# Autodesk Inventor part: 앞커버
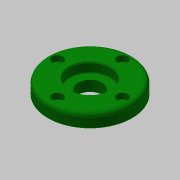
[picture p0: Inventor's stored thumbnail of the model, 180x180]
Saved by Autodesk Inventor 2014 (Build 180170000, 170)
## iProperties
Created: 2015-09
Part Number: 앞커버
Material: 알루미늄 6061
Document SubType Name: Modeling
Designer: mduedu
Density: 1 g/cm^3
Appearance: 진녹색
Author: mduedu
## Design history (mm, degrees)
sketch "스케치1"
  geometry: L1 (0, 7.5)-(0, -7.5); L2 (0, 7.5)-(31, 7.5); L3 (31, 7.5)-(31, -2.5); L4 (31, -2.5)-(17.5, -2.5); L5 (17.5, -2.5)-(17.5, -7.5); L6 (17.5, -7.5)-(0, -7.5); 2 further points
  constraints: 12 end point, 2 parallel, 2 perpendicular, 1 coincident, 1 horizontal, 1 midpoint, 1 vertical
  dimensions: "d0" = 15 distance of L1.start L1.end; "d1" = 62 diameter of L3 L1; "d2" = 35 diameter of L5 L1; "d3" = 10 distance of L2.end L3.end
revolve "회전1" sketch "스케치1" stored, may be unused: angle "d4" = 90 deg
hole "구멍1" diameter "d7" = 30; stored, may be unused: countersink angle "d11" = 90 deg, drill point angle "d13" = 0 deg; dims "d8" = 6, "d9" = 4, "d10" = 2, "d12" = 7.3, "d46" = 10, "d47" = 10
hole "구멍2" diameter "d16" = 18; stored, may be unused: countersink angle "d20" = 90 deg, drill point angle "d22" = 0 deg; dims "d14" = 10, "d15" = 10, "d17" = 6, "d18" = 4, "d19" = 2, "d21" = 7.3
fillet "모깎기2" dims "d48" = 3
chamfer "모따기2" distance "d26" = 0.7; stored, may be unused: second distance "d27" = 2, angle "d28" = 30 deg
fillet "모깎기1" dims "d29" = 0.3
sketch "스케치4" dims "d49" = 48
  geometry: 3 further points
  constraints: 2 vertical alignment, 1 coincident, 2 other
hole "구멍4" sketch "스케치4" at (0, 24) diameter "d50" = 4.5; stored, may be unused: countersink angle "d54" = 90 deg, drill point angle "d56" = 118 deg; dims "d51" = 6, "d52" = 8, "d53" = 4.4, "d55" = 8
chamfer "모따기3" distance "d43" = 1; stored, may be unused: second distance "d44" = 2, angle "d45" = 45 deg
node "솔리드1"
pattern_circular "원형 패턴1" dims angle "d58" = 360 deg
